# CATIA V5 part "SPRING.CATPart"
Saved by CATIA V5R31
Part number: SPRING
Revision: 01
Nomenclature: SPRING
Source: Unknown
Property "部品番号(B社)": "SPRING111111"
Property "部品名称(B社)": "SPRING"
Property "Version(B社)": "01"
Property "材質(B社)": "SWP-B"
Bounding box of the stored display mesh (mm): x -2.025 to 2.032, y -2.04 to 2.025, z 0 to 16.2
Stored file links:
  \\solize.local\damia\dept\DDE_Design\10_order\2305701_JAMA_変換検証STEP3_お手本モデル作成\work\03_東洋電装_スイッチ\10_CATIA_V5\SPRING.CATPart
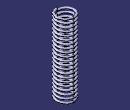
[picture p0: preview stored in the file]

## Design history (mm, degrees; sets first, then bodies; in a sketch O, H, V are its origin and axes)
WSupportSet1: ActiveGrid {3dwsupport RefPoint {point stored without definition}, 3DWOS ({wsupport Support xy-plane, RefPoint {3dwsupport}, GridIn {cartgrid Value 100, Stepbid1 0, Value 100, Stepbid2 0, Direction (1, 0, 0)}, GeometricData ({line type PtDir, Direction (1, 0, 0), Support xy-plane}; {line type PtDir, Direction (0, 1, 0), Support xy-plane})}; {wsupport Support yz-plane, RefPoint {3dwsupport}, GridIn {cartgrid Value 100, Stepbid1 0, Value 100, Stepbid2 0, Direction (0, 1, 0)}, GeometricData ({line type PtDir, Direction (0, 1, 0), Support yz-plane}; {line type PtDir, Direction (0, 0, 1), Support yz-plane})}; {wsupport Support zx-plane, RefPoint {3dwsupport}, GridIn {cartgrid Value 100, Stepbid1 0, Value 100, Stepbid2 0, Direction (0, 0, 1)}, GeometricData ({line type PtDir, Direction (0, 0, 1), Support zx-plane}; {line type PtDir, Direction (1, 0, 0), Support zx-plane})}), GeometricData ({line type PtDir, RefPoint {point stored without definition}, Direction (1, 0, 0), Support xy-plane}; {line type PtDir, RefPoint {point stored without definition}, Direction (0, 1, 0), Support xy-plane}; {line type PtDir, RefPoint {point stored without definition}, Direction (0, 1, 0), Support yz-plane}; {line type PtDir, RefPoint {point stored without definition}, Direction (0, 0, 1), Support yz-plane}; {line type PtDir, RefPoint {point stored without definition}, Direction (0, 0, 1), Support zx-plane}; {line type PtDir, RefPoint {point stored without definition}, Direction (1, 0, 0), Support zx-plane})}
Body1 "SPRING" (main body)
  Solid1: solid without history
